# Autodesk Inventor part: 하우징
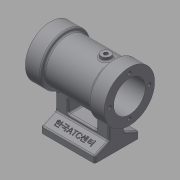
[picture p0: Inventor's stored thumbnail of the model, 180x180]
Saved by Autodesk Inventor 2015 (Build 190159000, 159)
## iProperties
Created: 2018-01
Part Number: 하우징
Material: 알루미늄 6061
Document SubType Name: Modeling
Designer: mduedu
Density: 2.71 g/cm^3
Appearance: 기본값
Mass: 74.6882 g
Surface Area: 127.588 cm^2
Volume: 27.5602 cm^3
Author: mduedu
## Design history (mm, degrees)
sketch "스케치1"
  geometry: L1 (-25, 0)-(25, 0); L2 (-25, 0)-(-25, 16); L3 (-25, 16)-(-15, 16); L4 (-15, 16)-(-15, 14); L5 (-15, 14)-(15, 14); L6 (15, 14)-(15, 16); L7 (15, 16)-(25, 16); L8 (25, 16)-(25, 0); 2 further points
  constraints: 16 end point, 3 parallel, 2 collinear, 2 perpendicular, 1 coincident, 1 horizontal, 1 midpoint, 1 vertical
  dimensions: "d0" = 50 distance of L1.start L1.end; "d2" = 10 distance of L2.end L3.end; "d3" = 10 distance of L6.end L7.end (= d2); "d4" = 32 diameter of L3 L1; "d5" = 28 diameter of L5 L1
revolve "회전1" sketch "스케치1" stored, may be unused: angle "d6" = 90 deg
hole "구멍1" diameter "d9" = 20; stored, may be unused: countersink angle "d13" = 90 deg, drill point angle "d15" = 118 deg; dims "d7" = 10, "d8" = 10, "d10" = 6, "d11" = 4, "d12" = 2, "d14" = 8
fillet "모깎기1" dims "d16" = 1
sketch "스케치2"
  geometry: L1 (0, 0)-(-34, 0); L2 (-34, 14)-(-34, -14); L3 (-34, 14)-(-30, 14); L4 (-30, 14)-(-26, 5); L5 (-26, 5)-(-13.077, 5); L6 (-26, -5)-(-13.077, -5); L7 (-30, -14)-(-26, -5); L8 (-34, -14)-(-30, -14); C1 r 10 at (0, 0) reference; A1 r 14 centre (0, 0) between (-13.077, 5) and (-13.077, -5); 2 further points
  constraints: 16 end point, 3 symmetric about line, 2 perpendicular, 2 point on circle, 1 centre point, 1 coincident, 1 horizontal, 1 midpoint, 1 parallel, 2 other
  dimensions: "d17" = 34 distance of L1.end L1.start; "d18" = 28 distance between parallel lines of L8 L3; "d19" = 10 distance between parallel lines of L6 L5; "d20" = 4 distance of L2.end L7.start; "d21" = 8 distance from line of L6.start L2
extrude "돌출1" join sketch "스케치2" stored distance "d22" = 34; taper "d23" = 0 deg
sketch "스케치3"
  geometry: L1 (-9, -16)-(9, -16); L2 (9, -16)-(9, -24); L3 (9, -24)-(-9, -24); L4 (-9, -24)-(-9, -16); L5 (-17, -15.199)-(-17, -26) reference; L6 (17, -26)-(17, -15.199) reference; L7 (-17, -34)-(17, -34) reference; 1 further point
  constraints: 8 end point, 2 parallel, 1 horizontal, 1 perpendicular
  dimensions: "d24" = 8 distance between parallel lines of L4 L5; "d25" = 8 distance between parallel lines of L2 L6; "d26" = 10 distance between parallel lines of L3 L7; "d27" = 8 distance of L1.end L2.end
extrude "돌출2" cut sketch "스케치3" stored distance "d28" = 34; taper "d29" = 0 deg
fillet "모깎기2" dims "d30" = 1
fillet "모깎기3" dims "d31" = 1
fillet "모깎기4" dims "d32" = 1
fillet "모깎기5" dims "d33" = 1
fillet "모깎기6" dims "d34" = 1
sketch "스케치4"
  geometry: 4 further points
  constraints: 4 other
hole "구멍2" sketch "스케치4" at (-12.5, 0), (0, -12.5), (12.5, 0), (0, 12.5) diameter "d35" = 2.459; stored, may be unused: countersink angle "d39" = 90 deg, drill point angle "d41" = 120 deg; dims "d36" = 5.5, "d37" = 4, "d38" = 2, "d40" = 7
sketch "스케치5"
  geometry: 4 further points
  constraints: 4 other
hole "구멍4" sketch "스케치5" at (-12.5, 0), (0, -12.5), (12.5, 0), (0, 12.5) diameter "d42" = 2.459; stored, may be unused: countersink angle "d46" = 90 deg, drill point angle "d48" = 120 deg; dims "d43" = 5.5, "d44" = 4, "d45" = 2, "d47" = 7
sketch "스케치6"
  geometry: 2 further points
  constraints: 2 other
hole "구멍5" sketch "스케치6" at (7, 14), (25, 14) diameter "d49" = 2.459; stored, may be unused: countersink angle "d53" = 90 deg, drill point angle "d55" = 120 deg; dims "d50" = 6.9, "d51" = 4, "d52" = 2, "d54" = 8.4
node "작업 평면1"
sketch "스케치7"
  geometry: L1 (-25, 16)-(-25, -16) reference; C1 r 3 at (-10, 0); 1 further point
  constraints: 1 centre point, 1 horizontal alignment
  dimensions: "d57" = 6 diameter of C1; "d60" = 15 distance from line of C1.centre L1
extrude "돌출3" join sketch "스케치7" stored distance "d61" = 10; taper "d62" = 0 deg
fillet "모깎기7" dims "d63" = 1
hole "구멍6" diameter "d66" = 2.459; stored, may be unused: countersink angle "d70" = 90 deg, drill point angle "d72" = 118 deg; dims "d64" = 10, "d65" = 10, "d67" = 6, "d68" = 4, "d69" = 2, "d71" = 8
sketch "스케치8"
  geometry: L1 (-1, 0)-(0, 0) reference; L2 (0, 0)-(0, 8.549) reference; L3 (0, 8.549)-(-1, 8.549) reference; L4 (-1, 8.549)-(-1, 0) reference; L5 (32, 0)-(33, 0) reference; L6 (33, 0)-(33, 8.549) reference; L7 (32, 8.549)-(33, 8.549) reference; L8 (32, 8.549)-(32, 0) reference; 3 further points
  constraints: 1 horizontal alignment, 1 midpoint, 1 vertical alignment, 1 other
feature "엠보싱1" sketch "스케치8" dims "d73" = 0.5, "d74" = 0
node "솔리드1"
node "투영된 루프1"
node "투영된 루프2"
node "절단 모서리 투영1"
other parameters: "d56" = 16
